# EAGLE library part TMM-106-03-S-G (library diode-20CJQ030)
Samtec TMM Board-Stacker serie. Single Row
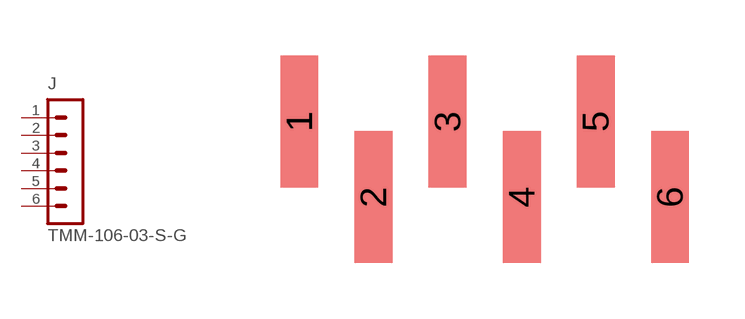
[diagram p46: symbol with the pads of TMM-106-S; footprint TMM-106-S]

Designator prefix J

## TMM-106-03-S-G  [TMM-106-S]
1  1  pas
2  2  pas
3  3  pas
4  4  pas
5  5  pas
6  6  pas

## Footprint TMM-106-S (pad centres in mm)
smd 1.02 x 3.56: 1 -3,1.022; 2 -1,-1.022; 3 1,1.022; 4 3,-1.022; 5 5,1.022; 6 7,-1.022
